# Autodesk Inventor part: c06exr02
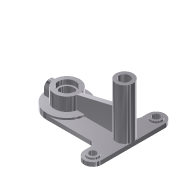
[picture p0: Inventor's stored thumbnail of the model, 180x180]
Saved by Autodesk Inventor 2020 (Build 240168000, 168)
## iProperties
Created: 2001-12
Part Number: c06exr02
Document SubType Name: Modeling
Material: Generic
Density: 1 g/cm^3
Appearance: Metal-AL-6061 (Polished)
Control State: 0
Master: False
Checked Out: False
Shininess: 77.0
Length Units: 11269
Angle Units: 11279
Time Units: 11290
Mass Units: 11283
Length Display Precision: 3
Angle Display Precision: 2
Density: 0.0
Volumn: 0.0
Area: 0.0
PropertySet Name: Model Information
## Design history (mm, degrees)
sketch "Sketch1"
  geometry: L1 (46.121, -53.4)-(46.121, 56.6); L2 (16.121, 56.6)-(16.121, 36.6); L3 (16.121, 36.6)-(-68.879, 36.6); L4 (-68.879, -33.4)-(16.121, -33.4); L5 (16.121, -33.4)-(16.121, -53.4); A1 r 15 centre (31.121, 56.6) between (46.121, 56.6) and (16.121, 56.6); A2 r 35 centre (-68.879, 1.6) between (-68.879, 36.6) and (-68.879, -33.4); A3 r 15 centre (31.121, -53.4) between (16.121, -53.4) and (46.121, -53.4)
  constraints: 10 end point, 6 point on circle, 5 tangent, 3 centre point, 3 parallel, 2 equal length, 1 equal radius, 1 perpendicular, 1 vertical
  dimensions: "d0" = 15 radius of A1; "d1" = 110 distance of L1.start L1.end; "d2" = 100 horizontal distance of A3.centre A2.centre; "d3" = 35 radius of A2
extrude "Extrusion1" new body sketch "Sketch1" distance "d4" = 7; taper "d5" = 0 deg
sketch "Sketch2"
  geometry: C1 r 10 at (31.121, 56.6); C2 r 10 at (31.121, -53.4); C3 r 35 at (-68.879, 1.6); A1 r 35 centre (-68.879, 1.6) between (-68.879, 36.6) and (-68.879, -33.4) reference; A2 r 15 centre (31.121, 56.6) between (46.121, 56.6) and (16.121, 56.6) reference; A3 r 15 centre (31.121, -53.4) between (16.121, -53.4) and (46.121, -53.4) reference
  constraints: 3 centre point, 3 concentric, 2 equal radius
  dimensions: "d45" = 20 diameter of C1
extrude "Extrusion2" join sketch "Sketch2" distance "d6" = 3; taper "d7" = 0 deg
sketch "Sketch3"
  geometry: C1 r 22 at (0, 0); 1 further point
  constraints: 1 centre point, 1 coincident
  dimensions: "d8" = 44 diameter of C1
extrude "Extrusion3" join sketch "Sketch3" distance "d9" = 23; taper "d10" = 0 deg
sketch "Sketch4"
  geometry: L1 (46.121, 56.6)-(46.121, -53.4) reference; L2 (-68.879, 36.6)-(16.121, 36.6) reference; C1 r 15 at (31.121, 1.6)
  constraints: 1 centre point
  dimensions: "d11" = 30 diameter of C1; "d12" = 15 distance from line of L1 C1.centre; "d13" = 35 distance from line of L2 C1.centre
extrude "Extrusion4" join sketch "Sketch4" distance "d14" = 88; taper "d15" = 0 deg
workplane "Work Plane1"
sketch "Sketch5"
  geometry: L1 (22, 33.1)-(85, 48); L2 (0, 7)-(35, 7) reference; L3 (85, 0)-(85, 7) reference; L4 (115, 0)-(115, 7) reference; L5 (115, 0)-(85, 0) reference
  constraints: 2 end point
  dimensions: "d17" = 26.1 distance from line of L2 L1.start; "d18" = 63 distance from line of L3 L1.start; "d19" = 30 distance from line of L4 L1.end; "d20" = 48 distance from line of L5 L1.end
feature "Rib1" sketch "Sketch5" dims "d21" = 1, "d22" = 8
workplane "Work Plane2"
workplane "Work Plane3"
sketch "Sketch7"
  geometry: L1 (10, 0)-(10, 10); L2 (-10, 10)-(-10, 0); L3 (-10, 0)-(10, 0); L4 (55, -10)-(55, -3) reference; A1 r 10 centre (0, 10) between (10, 10) and (-10, 10); 2 further points
  constraints: 6 end point, 2 point on circle, 2 tangent, 1 centre point, 1 parallel, 1 perpendicular, 1 vertical
  dimensions: "d30" = 10 radius of A1; "d34" = 55 distance from line of L4 A1.centre; "d35" = 10 distance of L1.start L1.end
extrude "Extrusion6" join sketch "Sketch7" stored distance "d36" = 88; taper "d37" = 0 deg
sketch "Sketch8"
  geometry: C1 r 10 at (0, 0) reference
hole "Hole1" sketch "Sketch8" at (0, 0) diameter "d38" = 12; stored, may be unused: countersink angle "d42" = 82 deg, drill point angle "d44" = 118 deg; dims "d39" = 6, "d40" = 4, "d41" = 2, "d43" = 8
mirror "Mirror1"
sketch "Sketch9"
  geometry: C1 r 10 at (0, 0)
  constraints: 1 centre point
hole "Hole2" sketch "Sketch9" at (0, 0) diameter "d52" = 18; stored, may be unused: drill point angle "d47" = 118 deg, countersink angle "d48" = 82 deg; dims "d46" = 6, "d49" = 2, "d50" = 4, "d51" = 8
sketch "Sketch10"
  geometry: C1 r 10 at (0, 0)
  constraints: 1 centre point
hole "Hole3" sketch "Sketch10" at (0, 0) diameter "d59" = 24; stored, may be unused: drill point angle "d54" = 118 deg, countersink angle "d55" = 82 deg; dims "d53" = 6, "d56" = 8, "d57" = 30, "d58" = 8
sketch "Sketch11"
  geometry: C1 r 10 at (0, 0)
  constraints: 1 centre point
hole "Hole4" sketch "Sketch11" at (0, 0) diameter "d66" = 10; stored, may be unused: drill point angle "d61" = 0 deg, countersink angle "d62" = 82 deg; dims "d60" = 6, "d63" = 2, "d64" = 4, "d65" = 8
fillet "Fillet1" dims "d67" = 10
body "Solid1"
other parameters: "d16" = -35, "d29" = -8
